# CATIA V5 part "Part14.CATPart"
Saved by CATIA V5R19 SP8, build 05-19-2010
Part number: Entretoise
Bounding box of the stored display mesh (mm): x -51.986 to 51.986, y -51.986 to 51.986, z 57.494 to 187.494
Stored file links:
  G:\EU_thinkMotion\CFAO_2010\MMS_groupe1\MMS_groupe1\OK\ppiault\piault\piault_cfao\Part14.CATPart
  D:\Catia\Finaltest.CATProduct
  G:\Catia Projet\CFAO2\Product2.CATProduct
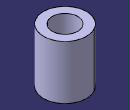
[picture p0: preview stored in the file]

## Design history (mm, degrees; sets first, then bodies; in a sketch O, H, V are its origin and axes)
Parameters
  epaisseur_entretoise = 18 mm
  Longueur_entretoise = 130 mm
External parameters (linked from other documents)
  External.LongueurEntretoise = 130 mm
Body1 (main body)
  Sketch1 on yz-plane, origin (0, 0, 0), H (0, 1, 0), V (0, 0, 1)
    line L1 (-52, 187.4938) -> (-31, 187.4938)
    line L2 (-31, 187.4938) -> (-31, 57.4938)
    line L3 (-31, 57.4938) -> (-52, 57.4938)
    line L4 (-52, 57.4938) -> (-52, 187.4938)
    length L2 = 130 {= External.LongueurEntretoise}
    distance V L4 = 52
    distance L2 V = 31
    vertical: L2 V, L4 V
  Shaft1: profile Sketch1, axis Sketch1.V, angle 360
